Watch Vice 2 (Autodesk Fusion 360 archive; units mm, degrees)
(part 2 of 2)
sketch "Sketch5" plane through (0, 0, 0) normal (0, 1, 0) x axis (1, 0, 0)
  line L1 (20.8174, -7.0022) -> (-20, -7.0022)
  line L2 (-20, -1.4022) -> (20.8174, -1.4022)
  line L3 (6.8871, -1.4022) -> (4.8489, -7.0022)
  line L4 (0, -1.4022) -> (0, 0)
  line L5 (0, -7.0022) -> (0, -1.4022)
  line L6 (6.6743, -1.4022) -> (4.636, -7.0022)
  line L7 (0, -6.0022) -> (5, -6.0022)
  line L8 (-6.8871, -1.4022) -> (-4.8489, -7.0022)
  line L9 (-6.6743, -1.4022) -> (-4.636, -7.0022)
  line L10 (0, -6.0022) -> (-5, -6.0022)
  point P13 (5, -6.0022)
  point P14 (0, -6.0022)
  dimension "d47" distance L3 L6 = 0.2
  dimension "d48" angle L2 L6 = 70
  dimension "d49" distance P13 P14 = 5
  dimension "d50" distance L1 L7 = 1
extrude "Extrude7" cut sketch "Sketch5" profile of L1 L2 L3 L5 L6 L7 L8 L9 L10 distance 10 bodies "Clamp Jaw Center", "Clamp Jaws 2"
sketch "Sketch6" plane through (0, 0, 7.0022) normal (0, 0, 1) x axis (-1, 0, 0)
  line L1 (-4.8489, 5) -> (-4.8489, -5)
  line L2 (-19.1013, 5) -> (-4.8489, 5)
  line L3 (-4.8489, -5) -> (-19.1013, -5)
  line L4 (14, -2) -> (16, -2)
  line L5 (16, 2) -> (14, 2)
  line L6 (6.6743, -5) -> (-6.6743, -5)
  line L7 (0, -5) -> (0, 0)
  line L8 (0, 0) -> (14, 0)
  line L9 (16, 0) -> (14, 0)
  line L10 (-14, -2) -> (-16, -2)
  line L11 (-16, 2) -> (-14, 2)
  line L12 (1.7, -4) -> (1.7, -6.1)
  line L13 (-1.7, -4) -> (1.7, -4)
  line L14 (-1.7, -6.1) -> (-1.7, -4)
  line L15 (-1.9, -3.8) -> (1.9, -3.8)
  line L16 (-1.9, -6.1) -> (-1.9, -3.8)
  line L17 (1.9, -3.8) -> (1.9, -6.1)
  line L18 (1.7, 4) -> (1.7, 6.1)
  line L19 (1.9, 3.8) -> (1.9, 6.1)
  line L20 (-1.9, 6.1) -> (-1.9, 3.8)
  line L21 (-1.7, 6.1) -> (-1.7, 4)
  line L22 (-1.7, 4) -> (1.7, 4)
  line L23 (-1.9, 3.8) -> (1.9, 3.8)
  arc A1 centre (-19.1697, 3.3264) radius 1.6 clockwise from (-20.7691, 3.3723) to (-19.4506, 4.9016)
  arc A2 centre (96.8326, 0) radius 117.65 clockwise from (-20.7691, -3.3723) to (-20.7691, 3.3723)
  arc A3 centre (-19.1697, -3.3264) radius 1.6 clockwise from (-19.4506, -4.9016) to (-20.7691, -3.3723)
  arc A4 centre (14, 0) radius 2 clockwise from (14, -2) to (14, 2)
  arc A5 centre (16, 0) radius 2 clockwise from (16, 2) to (16, -2)
  circle C1 centre (15, 0) radius 1.95
  arc A6 centre (-14, 0) radius 2 clockwise from (-14, 2) to (-14, -2)
  arc A7 centre (-16, 0) radius 2 clockwise from (-16, -2) to (-16, 2)
  circle C2 centre (-15, 0) radius 1.95
  circle C3 centre (0, 0) radius 1.75
  arc A8 centre (0, -6.1) radius 1.7 clockwise from (1.7, -6.1) to (-1.7, -6.1)
  arc A9 centre (0, -6.1) radius 1.9 clockwise from (1.9, -6.1) to (-1.9, -6.1)
  arc A10 centre (0, 6.1) radius 1.7 clockwise from (-1.7, 6.1) to (1.7, 6.1)
  arc A11 centre (0, 6.1) radius 1.9 clockwise from (-1.9, 6.1) to (1.9, 6.1)
  arc A12 centre (-19.7754, 6.7228) radius 1.85 clockwise from (-19.1013, 5) to (-19.4506, 4.9016)
  arc A13 centre (-19.7754, -6.7228) radius 1.85 clockwise from (-19.4506, -4.9016) to (-19.1013, -5)
  point P13 (14, -2)
  point P16 (16, -2)
  point P1 (0, 0)
  point P21 (15, 0)
  point P32 (1.7, -6.1)
  dimension "d53" diameter A5 = 4
  dimension "d54" diameter C1 = 3.9 (= "d53 - 0.1 mm")
  dimension "d55" distance P13 P16 = 2
  dimension "d56" distance P1 P21 = 15
  dimension "d61" diameter C3 = 3.5
  dimension "d63" radius A8 = 1.7 (= "( 3.6 / 2 ) * 1 mm - 0.1 mm")
  dimension "d64" distance L6 P32 = 1.1
  dimension "d65" distance L8 L13 = 4
  dimension "d66" = 0.2
extrude "Extrude8" add sketch "Sketch6" profile of C1 C2 along normal blind 2
extrude "Extrude9" cut sketch "Sketch6" profile of A5 A4 L4 L5 C1 A6 L10 A7 C2 L11 along normal blind 7 and against normal blind 1
extrude "Extrude13" cut sketch "Sketch6" profile of C3 no distance stored
extrude "Extrude11" sketch "Sketch6" profile of L6 A8 L12 L14 A10 L18 L21 L22 to an object
extrude "Extrude16" cut sketch "Sketch6" profile of L6 A8 L12 L13 L14 L16 L15 L17 A9 A10 A11 L18 L19 L20 L21 L22 L23 to an object
combine "Combine1" bodies "Clamp Upper", "Clamp Jaw 1", "Clamp Jaw Center", "Clamp Jaws 2"
sketch "Sketch13" plane through (0, 0, 0) normal (0, 0, 1) x axis (-1, 0, 0)
  circle C1 centre (-33, 0) radius 2.025
  circle C2 centre (33, 0) radius 2.025
  circle C3 centre (-33, 0) radius 3.5
  circle C4 centre (33, 0) radius 3.5
  dimension "d133" diameter C3 = 7
extrude "Extrude21" add sketch "Sketch13" along normal blind 2.75
sketch "Sketch15" plane through (0, 0, 10) normal (0, 0, 1) x axis (-1, 0, 0)
  circle C1 centre (0, 0) radius 19
  circle C2 centre (0, 0) radius 3.6
  dimension "d139" diameter C1 = 38
extrude "Extrude23" cut sketch "Sketch15" against normal blind 1
sketch "Sketch14" plane through (0, 0, 8) normal (0, 0, 1) x axis (-1, 0, 0)
  circle C1 centre (0, 0) radius 3.5
  dimension "d136" diameter C1 = 7
extrude "Extrude22" add sketch "Sketch14" along normal blind 2.75
named bodies: "Clamp", "Clamp Upper", "Clamp Jaw 1", "Clamp Jaw Center", "Clamp Jaws 2"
